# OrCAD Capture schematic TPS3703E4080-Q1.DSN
size A; title: TPS3703-Q1 High-Accuracy Window Supervisor; rev: 1.0; note: SBVS344 –JUNE 2018
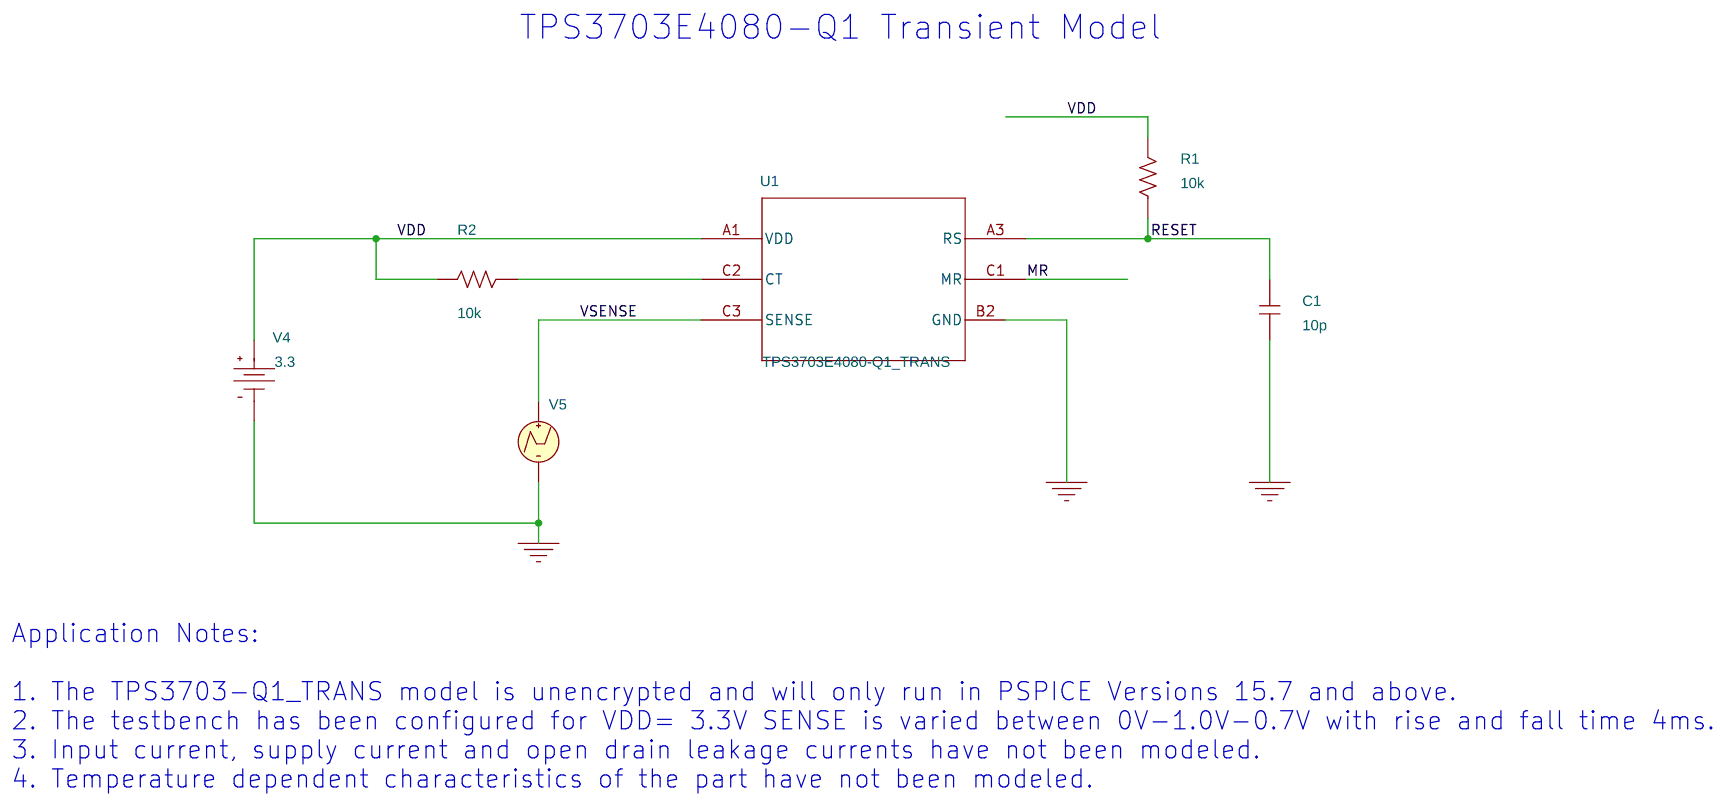
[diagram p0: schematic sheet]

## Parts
C1  10p  [RAD/CK05]
R1  10k  [AX/RC05]
R2  10k  [AX/RC05]
U1  TPS3703E4080-Q1_TRANS  [YKA0005AFAF]
V4  VDC
V5  VPWL

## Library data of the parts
C1 = C
R1 R2 = R
U1 = TPS3703A4330-Q1_TRANS_0
V4 = VDC: DC: 3.3
V5 = VPWL: PSpiceTemplate: V^@REFDES %+ %- ?DC|DC @DC| ?AC|AC @AC|\n+PWL @T1 @V1 @T2 @V2 #T3/@T3 @V3/ #T4/@T4 @V4/ #T5/@T5 @V5/ #T6/@T6 @V6/ #T7/@T7 @V7/ #T8/@T8 @V8/ #T9/@T9 @V9/ #T10/@T10 @V10/; T1: 0; T2: 12m; T3: 16m; T4: 240m; T5: 244m; T6: 450m; T7: 454m; T8: 662m; T9: 666m; V1: 0; V2: 0; V3: 1; V4: 1; V5: 1; V6: 0.7; V7: 0.7; V8: 0; V9: 0

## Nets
VDD: R1.2 R2.2 U1.A1(VDD) V4.0(+)
0: C1.1 U1.B2(GND) V4.1(-) V5.2(-)
MR: U1.C1(MR)
RESET: C1.2 R1.1 U1.A3(RS)
VSENSE: U1.C3(SENSE) V5.1(+)
N16776067: R2.1 U1.C2(CT)

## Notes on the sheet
- TPS3703E4080-Q1 Transient Model
- Application Notes:
  1. The TPS3703-Q1_TRANS model is unencrypted and will only run in PSPICE Versions 15.7 and above.
  2. The testbench has been configured for VDD= 3.3V SENSE is varied between 0V-1.0V-0.7V with rise and fall time 4ms.
  3. Input current, supply current and open drain leakage currents have not been modeled.
  4. Temperature dependent characteristics of the part have not been modeled.
